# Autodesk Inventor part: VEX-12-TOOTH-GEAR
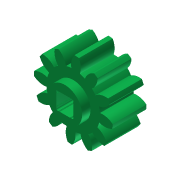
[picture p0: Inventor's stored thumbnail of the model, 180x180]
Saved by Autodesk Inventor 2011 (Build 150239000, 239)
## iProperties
Created: 2007-08
Part Number: VEX-12-TOOTH-GEAR
Material: ABS Plastic
Document SubType Name: Modeling
Density: 1.06 g/cm^3
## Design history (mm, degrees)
feature "Base1"
workplane "Work Plane1"
sketch "Sketch1"
  geometry: C1 r 3.25 at (1.136, 5.997) reference; A1 r 7.404 centre (1.136, 5.997) between (1.917, -1.366) and (2.735, -1.232) reference; A2 r 3 centre (0, 0) between (2.735, -1.232) and (2.735, 1.232) reference; A3 r 5.025 centre (1.136, 5.997) between (2.735, 1.232) and (3.647, 1.644) reference; A4 r 3 centre (6.381, 2.877) between (3.647, 1.644) and (5.494, 0.011) reference; A5 r 7.404 centre (1.136, 5.997) between (5.494, 0.011) and (6.135, 0.536) reference; A6 r 3 centre (3.15, 0.236) between (6.135, 0.536) and (4.903, 2.67) reference; A7 r 5.025 centre (1.136, 5.997) between (4.903, 2.67) and (5.487, 3.482) reference; A8 r 3 centre (7.238, 5.918) between (5.487, 3.482) and (7.903, 2.992) reference; A9 r 7.404 centre (1.136, 5.997) between (7.903, 2.992) and (8.196, 3.767) reference; A10 r 3 centre (5.761, 2.015) between (8.196, 3.767) and (6.061, 5) reference; A11 r 5.025 centre (1.136, 5.997) between (6.061, 5) and (6.161, 5.995) reference; A12 r 3 centre (6.46, 8.98) between (6.161, 5.995) and (8.498, 6.778) reference; A13 r 7.404 centre (1.136, 5.997) between (8.498, 6.778) and (8.365, 7.596) reference; A14 r 3 centre (7.132, 4.861) between (8.365, 7.596) and (5.9, 7.596) reference; A15 r 5.025 centre (1.136, 5.997) between (5.9, 7.596) and (5.489, 8.508) reference; A16 r 3 centre (4.255, 11.242) between (5.489, 8.508) and (7.121, 10.355) reference; A17 r 7.404 centre (1.136, 5.997) between (7.121, 10.355) and (6.597, 10.996) reference; A18 r 3 centre (6.897, 8.011) between (6.597, 10.996) and (4.462, 9.764) reference; A19 r 5.025 centre (1.136, 5.997) between (4.462, 9.764) and (3.65, 10.348) reference; A20 r 3 centre (1.215, 12.099) between (3.65, 10.348) and (4.14, 12.764) reference; A21 r 7.404 centre (1.136, 5.997) between (4.14, 12.764) and (3.365, 13.057) reference; A22 r 3 centre (5.118, 10.622) between (3.365, 13.057) and (2.133, 10.922) reference; A23 r 5.025 centre (1.136, 5.997) between (2.133, 10.922) and (1.138, 11.022) reference; A24 r 3 centre (-1.847, 11.321) between (1.138, 11.022) and (0.354, 13.359) reference; A25 r 7.404 centre (1.136, 5.997) between (0.354, 13.359) and (-0.464, 13.226) reference; A26 r 3 centre (2.271, 11.993) between (-0.464, 13.226) and (-0.464, 10.761) reference; A27 r 5.025 centre (1.136, 5.997) between (-0.464, 10.761) and (-1.375, 10.35) reference; A28 r 3 centre (-4.11, 9.116) between (-1.375, 10.35) and (-3.223, 11.982) reference; A29 r 7.404 centre (1.136, 5.997) between (-3.223, 11.982) and (-3.864, 11.458) reference; A30 r 3 centre (-0.879, 11.758) between (-3.864, 11.458) and (-2.632, 9.323) reference; A31 r 5.025 centre (1.136, 5.997) between (-2.632, 9.323) and (-3.216, 8.511) reference; A32 r 3 centre (-4.967, 6.076) between (-3.216, 8.511) and (-5.631, 9.001) reference; A33 r 7.404 centre (1.136, 5.997) between (-5.631, 9.001) and (-5.925, 8.226) reference; A34 r 3 centre (-3.49, 9.979) between (-5.925, 8.226) and (-3.79, 6.994) reference; A35 r 5.025 centre (1.136, 5.997) between (-3.79, 6.994) and (-3.89, 5.999) reference; A36 r 3 centre (-4.189, 3.014) between (-3.89, 5.999) and (-6.227, 5.215) reference; A37 r 7.404 centre (1.136, 5.997) between (-6.227, 5.215) and (-6.093, 4.397) reference; A38 r 3 centre (-4.861, 7.132) between (-6.093, 4.397) and (-3.628, 4.397) reference; A39 r 5.025 centre (1.136, 5.997) between (-3.628, 4.397) and (-3.217, 3.486) reference; A40 r 3 centre (-1.984, 0.751) between (-3.217, 3.486) and (-4.85, 1.638) reference; A41 r 7.404 centre (1.136, 5.997) between (-4.85, 1.638) and (-4.325, 0.997) reference; A42 r 3 centre (-4.625, 3.982) between (-4.325, 0.997) and (-2.19, 2.229) reference; A43 r 5.025 centre (1.136, 5.997) between (-2.19, 2.229) and (-1.379, 1.645) reference; A44 r 3 centre (1.057, -0.106) between (-1.379, 1.645) and (-1.869, -0.77) reference; A45 r 7.404 centre (1.136, 5.997) between (-1.869, -0.77) and (-1.094, -1.064) reference; A46 r 3 centre (-2.846, 1.371) between (-1.094, -1.064) and (0.139, 1.071) reference; A47 r 5.025 centre (1.136, 5.997) between (0.139, 1.071) and (1.134, 0.971) reference; A48 r 3 centre (4.119, 0.672) between (1.134, 0.971) and (1.917, -1.366) reference; 1 further point
  constraints: 1 coincident, 3 other
body "Solid1"
